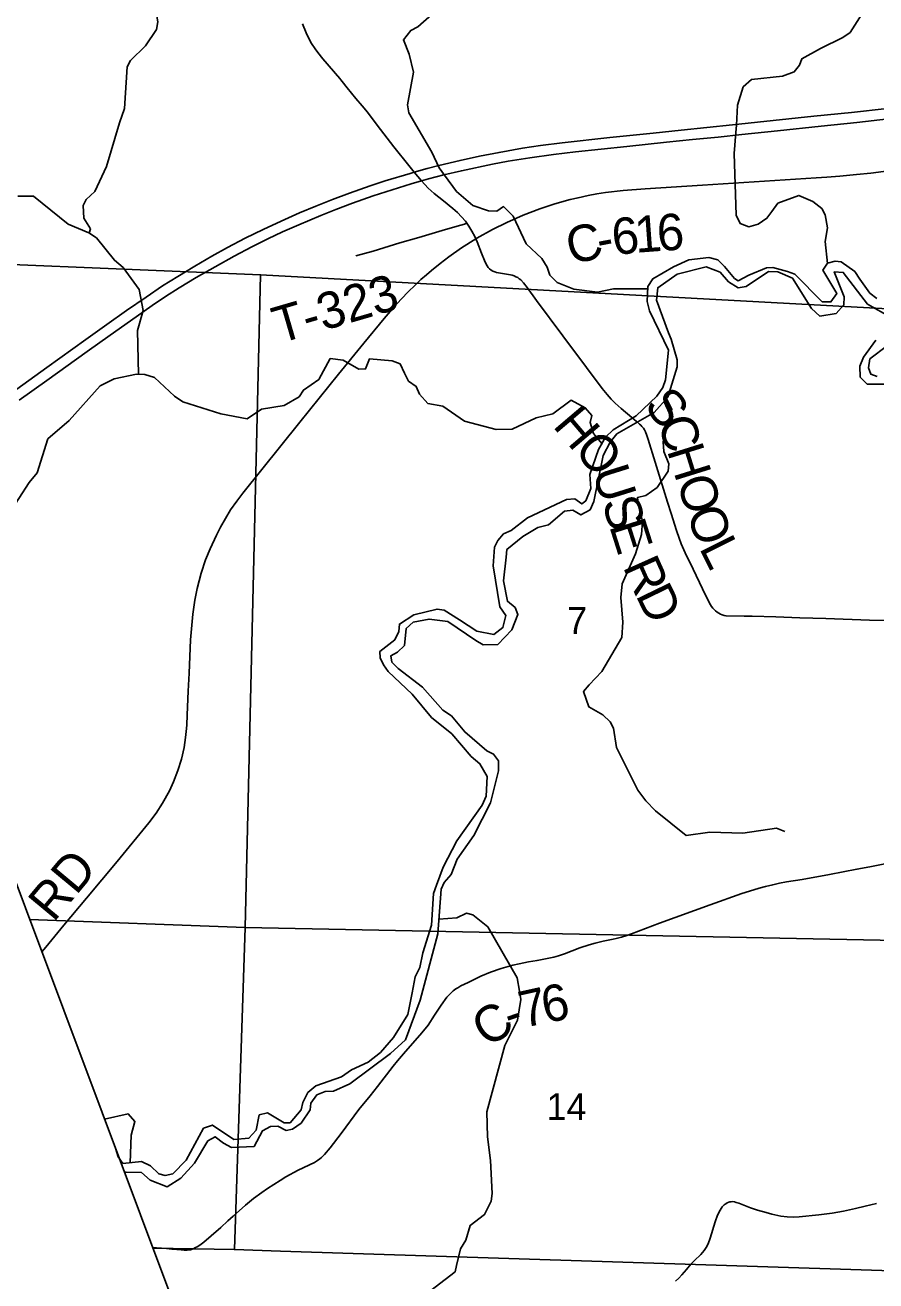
# Model space of a CAD drawing. Extents: x 0 to 34, y 0 to 22.
# Drawn here: x 26.74 to 28.066, y 15.361 to 17.319 of the extents above; entities that cross this region are included whole.
import ezdxf

# ---------------------------------------------------------------- set-up
doc = ezdxf.new("R2010")
doc.units = 0
for name, color, linetype in [('GM_X_County_Road', 7, 'Continuous'), ('GM_X_County_Road_Text', 7, 'Continuous'), ('GM_X_Minor_River', 7, 'Continuous'), ('GM_X_Section', 7, 'Continuous'), ('GM_X_Section_Text', 7, 'Continuous'), ('GM_X_State_Route', 7, 'Continuous'), ('GM_X_Township_Road', 7, 'Continuous'), ('GM_X_Township_Road_Text', 7, 'Continuous'), ('SH_Text', 7, 'Continuous')]:
    doc.layers.add(name, color=color, linetype=linetype)

msp = doc.modelspace()

# ---------------------------------------------------------------- linework, layer by layer
at = {"layer": 'GM_X_County_Road'}
for points in [[(27.4423, 16.9857), (27.4438, 16.9866), (27.4682, 17.0003), (27.4904, 17.0113), (27.5159, 17.0225), (27.542, 17.0326), (27.5655, 17.0403), (27.5895, 17.0468), (27.6017, 17.0497), (27.6176, 17.0531), (27.6308, 17.0555), (27.6442, 17.0578), (27.6719, 17.0611), (27.7063, 17.0637), (27.7954, 17.0692), (27.9725, 17.0806), (27.9895, 17.0818), (28.0098, 17.0832), (28.0357, 17.0857), (28.0579, 17.088), (28.0778, 17.0905), (28.1024, 17.0939), (28.1087, 17.095)], [(26.7658, 15.8742), (26.772, 15.8816), (26.8004, 15.9156), (26.8357, 15.958), (26.8836, 16.0152), (26.933, 16.0753), (26.9441, 16.0903), (26.9541, 16.1061), (26.9648, 16.1251), (26.9714, 16.1393), (26.9781, 16.1568), (26.9835, 16.1747), (26.9877, 16.1929), (26.9901, 16.2083), (26.9911, 16.2178), (26.9919, 16.2275), (26.9927, 16.2437), (26.9943, 16.2805), (26.9957, 16.3086), (26.9979, 16.3605), (27.0014, 16.4007), (27.0043, 16.4222), (27.008, 16.4404), (27.0145, 16.4644), (27.0213, 16.485), (27.0281, 16.5023), (27.0382, 16.5238), (27.0444, 16.5359), (27.052, 16.5498), (27.0602, 16.5629), (27.0701, 16.5766), (27.0792, 16.589), (27.1683, 16.6996), (27.2285, 16.7747), (27.2679, 16.8228), (27.2993, 16.8613), (27.3154, 16.8801), (27.326, 16.8914), (27.3374, 16.9035), (27.3473, 16.9131), (27.3568, 16.9221), (27.3652, 16.9295), (27.3731, 16.9364), (27.3868, 16.9472), (27.4, 16.9574), (27.4202, 16.9718), (27.4423, 16.9857)], [(26.9385, 15.4132), (26.9448, 15.4129), (26.9602, 15.4115), (26.9687, 15.4107), (26.9766, 15.41), (26.9832, 15.4095), (26.9878, 15.4093), (26.9903, 15.4092), (26.9927, 15.4092), (26.9947, 15.4094), (26.9975, 15.4098), (26.9991, 15.4103), (27.0017, 15.4112), (27.0055, 15.4131), (27.0081, 15.4145), (27.0109, 15.416), (27.0144, 15.4184), (27.0184, 15.4216), (27.0298, 15.4315), (27.0447, 15.4445), (27.0559, 15.4549), (27.0643, 15.4623), (27.0833, 15.4792), (27.0958, 15.4896), (27.109, 15.4992), (27.1178, 15.5052), (27.1275, 15.5114), (27.1374, 15.5178), (27.1464, 15.5234), (27.1656, 15.5336), (27.1907, 15.5458), (27.1955, 15.5488), (27.1991, 15.5512), (27.2019, 15.5536), (27.2049, 15.5566), (27.2066, 15.5584), (27.2152, 15.5687), (27.2323, 15.5908), (27.2601, 15.6282), (27.2777, 15.6499), (27.2891, 15.6642), (27.3137, 15.696), (27.3203, 15.704), (27.3297, 15.715), (27.3584, 15.7477), (27.3678, 15.7599), (27.378, 15.7754), (27.3881, 15.7911), (27.3974, 15.8036), (27.4, 15.8067), (27.4039, 15.8104), (27.4069, 15.8131), (27.4112, 15.8163), (27.4143, 15.8182), (27.4192, 15.8211), (27.4302, 15.8265), (27.45, 15.836), (27.465, 15.8423), (27.4819, 15.8483), (27.4999, 15.8532), (27.51, 15.8556), (27.5244, 15.8583), (27.5379, 15.8608), (27.5559, 15.864), (27.5637, 15.8657), (27.5714, 15.8677), (27.5805, 15.8708), (27.6044, 15.8802), (27.6191, 15.885), (27.6282, 15.8876), (27.6408, 15.8906), (27.6564, 15.8939), (27.6612, 15.895), (27.6693, 15.8972), (27.6759, 15.8993), (27.6851, 15.9023), (27.7287, 15.9186), (27.8073, 15.9476), (27.8571, 15.965), (27.8689, 15.9689), (27.8838, 15.9734), (27.8935, 15.9761), (27.9049, 15.9788), (27.9153, 15.9811), (27.9263, 15.983), (27.9508, 15.9871), (27.9935, 15.9949), (28.0362, 16.0028), (28.0564, 16.0068), (28.0875, 16.013)]]:
    msp.add_lwpolyline(points, dxfattribs=at)
at = {"layer": 'GM_X_Minor_River'}
for points in [[(26.8399, 16.9945), (26.8418, 17.0014), (26.8315, 17.0177), (26.8303, 17.0374), (26.8352, 17.0469), (26.8487, 17.0595), (26.8668, 17.0986), (26.8869, 17.1662), (26.8948, 17.1887), (26.899, 17.2539), (26.9043, 17.2638), (26.9276, 17.2863), (26.9449, 17.3118), (26.9468, 17.3239), (26.9425, 17.347), (26.9406, 17.3595), (26.9127, 17.4198), (26.8967, 17.4455), (26.8591, 17.5429)], [(27.7104, 16.9077), (27.6568, 16.9076), (27.6319, 16.9022), (27.5951, 16.907), (27.569, 16.9175), (27.5579, 16.9288), (27.5537, 16.9414), (27.5453, 16.955), (27.521, 16.978), (27.5004, 17.0208), (27.4855, 17.0359), (27.475, 17.0287), (27.4621, 17.029), (27.4375, 17.0377), (27.4124, 17.0592), (27.3934, 17.0846), (27.3854, 17.0963), (27.3739, 17.1209), (27.3377, 17.1819), (27.3357, 17.1944), (27.345, 17.2456), (27.3384, 17.2737), (27.3296, 17.296), (27.3409, 17.3105), (27.3518, 17.3162), (27.3865, 17.3467)], [(27.9901, 16.9473), (27.9869, 16.9813), (27.9902, 17.0025), (27.9868, 17.023), (27.9814, 17.0328), (27.9674, 17.0438), (27.9457, 17.0532), (27.9132, 17.0413), (27.9035, 17.0284), (27.8959, 17.0177), (27.8823, 17.0086), (27.8676, 17.0043), (27.854, 17.0096), (27.8478, 17.0225), (27.8448, 17.1188), (27.8473, 17.1515), (27.8484, 17.1628), (27.8501, 17.194), (27.8587, 17.2224), (27.8719, 17.2339), (27.9203, 17.2394), (27.9385, 17.2459), (27.9468, 17.2561), (27.9505, 17.2664), (27.9796, 17.2821), (28.0143, 17.2993), (28.0256, 17.3073), (28.0437, 17.3358)], [(26.9164, 16.7744), (26.9152, 16.8427), (26.9241, 16.8739), (26.9175, 16.9065), (26.8928, 16.9409), (26.8791, 16.9522), (26.851, 16.9871), (26.8392, 16.995), (26.807, 17.0085), (26.753, 17.052), (26.7288, 17.0519)], [(28.0672, 16.8928), (28.0565, 16.9007), (28.0409, 16.9227), (28.0329, 16.9348), (28.0117, 16.9495), (28.0022, 16.951), (27.9905, 16.9479), (27.9833, 16.9369), (28.0047, 16.9005), (27.9957, 16.8872), (27.982, 16.8875), (27.9395, 16.9306), (27.9281, 16.9348), (27.905, 16.9411), (27.8951, 16.9403), (27.8679, 16.9292), (27.851, 16.9202), (27.8454, 16.924), (27.83, 16.9427), (27.8194, 16.9529), (27.8054, 16.9567), (27.774, 16.9528), (27.7502, 16.9421)], [(27.7502, 16.9421), (27.7181, 16.9234), (27.7105, 16.9112), (27.7095, 16.8877), (27.713, 16.8736), (27.7428, 16.8123), (27.738, 16.7656), (27.7339, 16.7538), (27.7245, 16.7401), (27.692, 16.7096), (27.6566, 16.6879), (27.6446, 16.6765), (27.6337, 16.6571), (27.6198, 16.618), (27.6214, 16.5964), (27.6136, 16.5773), (27.6075, 16.5724), (27.5965, 16.5803), (27.5837, 16.5791), (27.5228, 16.5505), (27.4972, 16.531), (27.4855, 16.5257), (27.4768, 16.5154), (27.4716, 16.5051), (27.4694, 16.4759), (27.4795, 16.4118), (27.4891, 16.3986), (27.4846, 16.3796), (27.4703, 16.3689), (27.4437, 16.3738), (27.4168, 16.3915), (27.3929, 16.4066), (27.3819, 16.4084), (27.3456, 16.3996), (27.3233, 16.3851), (27.3222, 16.3733), (27.3159, 16.3604), (27.2928, 16.3425), (27.2933, 16.3323), (27.2982, 16.3216), (27.3055, 16.311), (27.3431, 16.2759), (27.3732, 16.2396), (27.4051, 16.2139), (27.4351, 16.1787), (27.4488, 16.1674), (27.4599, 16.1477), (27.4585, 16.1166), (27.4521, 16.1025), (27.4126, 16.047), (27.3912, 16.0059), (27.3811, 15.9778), (27.3766, 15.9649), (27.3734, 15.9156), (27.36, 15.8727), (27.3552, 15.8499), (27.3478, 15.835), (27.3432, 15.81), (27.3362, 15.7766), (27.314, 15.7405), (27.294, 15.7173), (27.2744, 15.702), (27.2487, 15.6902), (27.2329, 15.6791), (27.1928, 15.6653), (27.1804, 15.6546), (27.1729, 15.6394), (27.1703, 15.6277), (27.1529, 15.6075), (27.1437, 15.6075), (27.1177, 15.6229), (27.1048, 15.6198), (27.1, 15.5963), (27.0887, 15.5834), (27.0652, 15.5818), (27.0318, 15.604), (27.0182, 15.5991), (26.9908, 15.5493), (26.9701, 15.5283), (26.958, 15.5256), (26.9485, 15.5279), (26.9356, 15.5407), (26.9212, 15.5471), (26.8924, 15.544), (26.8852, 15.5546), (26.8806, 15.5679), (26.876, 15.5807), (26.8758, 15.5807)], [(26.8944, 15.5311), (26.8974, 15.5304), (26.9212, 15.5301), (26.9349, 15.518), (26.9611, 15.5078), (26.9826, 15.5215), (27.0037, 15.5448), (27.0247, 15.5794), (27.0361, 15.5858), (27.049, 15.576), (27.0615, 15.5689), (27.0968, 15.5708), (27.1098, 15.5952), (27.1223, 15.6021), (27.1337, 15.6025), (27.1469, 15.5957), (27.1568, 15.5976), (27.17, 15.6072), (27.1843, 15.6277), (27.185, 15.638), (27.1948, 15.6513), (27.2076, 15.6566), (27.2205, 15.6571), (27.2458, 15.6681), (27.3096, 15.7158), (27.3329, 15.7371), (27.3554, 15.799), (27.3829, 15.9023), (27.3883, 15.9718), (27.3928, 15.9824), (27.4037, 15.9946), (27.4131, 16.0185), (27.4391, 16.0554), (27.4653, 16.1064), (27.4776, 16.1561), (27.4775, 16.1721), (27.4699, 16.1823), (27.4597, 16.1875), (27.4251, 16.217), (27.4042, 16.242), (27.3909, 16.2507), (27.359, 16.2866), (27.3214, 16.316), (27.3115, 16.3259), (27.3099, 16.3357), (27.3205, 16.3411), (27.3314, 16.3517), (27.3336, 16.3779), (27.3449, 16.3878), (27.3695, 16.3928), (27.3986, 16.3892), (27.4423, 16.3597), (27.4537, 16.3529), (27.4764, 16.3534), (27.4982, 16.3759), (27.508, 16.3998), (27.5034, 16.4108), (27.4916, 16.4206), (27.4854, 16.4525), (27.4894, 16.4896), (27.4909, 16.5014), (27.5154, 16.5216), (27.5392, 16.5357), (27.5558, 16.5396), (27.5803, 16.5609), (27.5936, 16.5625), (27.6061, 16.5553), (27.6204, 16.5633), (27.6261, 16.5759), (27.6409, 16.6478), (27.6515, 16.6686), (27.6621, 16.6815), (27.7201, 16.7151), (27.7416, 16.7387), (27.7561, 16.7858), (27.7561, 16.7972), (27.7469, 16.829), (27.7426, 16.8392), (27.7239, 16.89), (27.7257, 16.9094), (27.7559, 16.9307), (27.8013, 16.9419), (27.8229, 16.9336), (27.8362, 16.9185), (27.851, 16.9091)], [(26.8944, 15.5311), (26.8974, 15.5304), (26.9212, 15.5301), (26.9349, 15.518), (26.9611, 15.5078), (26.9826, 15.5215), (27.0037, 15.5448), (27.0247, 15.5794), (27.0361, 15.5858), (27.049, 15.576), (27.0615, 15.5689), (27.0968, 15.5708), (27.1098, 15.5952), (27.1223, 15.6021), (27.1337, 15.6025), (27.1469, 15.5957), (27.1568, 15.5976), (27.17, 15.6072), (27.1843, 15.6277), (27.185, 15.638), (27.1948, 15.6513), (27.2076, 15.6566), (27.2205, 15.6571), (27.2458, 15.6681), (27.3096, 15.7158), (27.3329, 15.7371), (27.3554, 15.799), (27.3829, 15.9023), (27.3883, 15.9718), (27.3928, 15.9824), (27.4037, 15.9946), (27.4131, 16.0185), (27.4391, 16.0554), (27.4653, 16.1064), (27.4776, 16.1561), (27.4775, 16.1721), (27.4699, 16.1823), (27.4597, 16.1875), (27.4251, 16.217), (27.4042, 16.242), (27.3909, 16.2507), (27.359, 16.2866), (27.3214, 16.316), (27.3115, 16.3259), (27.3099, 16.3357), (27.3205, 16.3411), (27.3314, 16.3517), (27.3336, 16.3779), (27.3449, 16.3878), (27.3695, 16.3928), (27.3986, 16.3892), (27.4423, 16.3597), (27.4537, 16.3529), (27.4764, 16.3534), (27.4982, 16.3759), (27.508, 16.3998), (27.5034, 16.4108), (27.4916, 16.4206), (27.4854, 16.4525), (27.4894, 16.4896), (27.4909, 16.5014), (27.5154, 16.5216), (27.5392, 16.5357), (27.5558, 16.5396), (27.5803, 16.5609), (27.5936, 16.5625), (27.6061, 16.5553), (27.6204, 16.5633), (27.6261, 16.5759), (27.6409, 16.6478), (27.6515, 16.6686), (27.6621, 16.6815), (27.7201, 16.7151), (27.7416, 16.7387), (27.7561, 16.7858), (27.7561, 16.7972), (27.7469, 16.829), (27.7426, 16.8392), (27.7239, 16.89), (27.7257, 16.9094), (27.7559, 16.9307), (27.8013, 16.9419), (27.8229, 16.9336), (27.8362, 16.9185), (27.851, 16.9091)], [(27.851, 16.9091), (27.8635, 16.9114), (27.8986, 16.9346), (27.9129, 16.9339), (27.9357, 16.9245), (27.9654, 16.8772), (27.9783, 16.8651), (28.0037, 16.8694), (28.0157, 16.8827), (28.0161, 16.8953), (28.0008, 16.9343), (28.0148, 16.9332), (28.0525, 16.884), (28.0896, 16.8629)], [(28.0659, 16.8275), (28.0464, 16.8013), (28.0408, 16.7872), (28.0412, 16.7701), (28.0522, 16.7588), (28.098, 16.759)], [(28.0677, 16.771), (28.0578, 16.7744), (28.0544, 16.7846), (28.0562, 16.7983), (28.0841, 16.8192)], [(27.6388, 16.6663), (27.6256, 16.6821), (27.6206, 16.6995), (27.6232, 16.7102), (27.6129, 16.7223), (27.5909, 16.734), (27.5623, 16.713), (27.5366, 16.7064), (27.4992, 16.6889), (27.4738, 16.6884), (27.4249, 16.7015), (27.3911, 16.7249), (27.3673, 16.729), (27.3547, 16.7434), (27.3494, 16.7555), (27.3372, 16.7638), (27.3311, 16.7763), (27.3242, 16.7907), (27.3121, 16.7956), (27.2765, 16.7985), (27.2705, 16.7829), (27.2599, 16.7825), (27.2356, 16.7964), (27.2155, 16.799), (27.1975, 16.7663), (27.1737, 16.7499), (27.167, 16.7393), (27.1439, 16.7259), (27.1084, 16.7201), (27.0861, 16.7052), (27.0452, 16.713), (26.9857, 16.7314), (26.9728, 16.7405), (26.9416, 16.7692), (26.9265, 16.7741), (26.9136, 16.7744), (26.8788, 16.7675), (26.8569, 16.7564), (26.8087, 16.7024), (26.7755, 16.6738), (26.7587, 16.6206), (26.7462, 16.6058), (26.6977, 16.5309)], [(27.7397, 16.7366), (27.748, 16.72), (27.7342, 16.6691), (27.7354, 16.6543), (27.7431, 16.6346), (27.742, 16.6236), (27.7247, 16.5978), (27.7073, 16.5855), (27.6944, 16.5824), (27.6952, 16.5726), (27.7018, 16.5453), (27.7004, 16.5248), (27.6914, 16.4948), (27.6704, 16.4477), (27.6682, 16.4264), (27.6715, 16.3881), (27.6697, 16.3642), (27.6388, 16.3109), (27.6192, 16.2904), (27.6102, 16.2797), (27.6186, 16.2558), (27.6403, 16.2438), (27.6517, 16.2329), (27.6567, 16.223), (27.6614, 16.1927), (27.695, 16.1261), (27.7072, 16.1094), (27.7221, 16.094), (27.77, 16.0555), (27.8071, 16.0606), (27.8583, 16.0589), (27.9109, 16.0668), (27.9238, 16.0619)], [(27.3847, 15.9249), (27.4128, 15.9271), (27.4276, 15.9344), (27.4378, 15.9318), (27.461, 15.9133), (27.5065, 15.8338), (27.5104, 15.8126), (27.5123, 15.7997), (27.5072, 15.7678), (27.4877, 15.7283), (27.4593, 15.6246), (27.4603, 15.5859), (27.465, 15.5491), (27.4679, 15.4972), (27.466, 15.4854), (27.4559, 15.4645), (27.4336, 15.4477), (27.4265, 15.4245), (27.4182, 15.4112), (27.4123, 15.385), (27.4101, 15.3755)], [(26.8635, 15.6135), (26.9003, 15.6217), (26.911, 15.6096), (26.9054, 15.5884), (26.9035, 15.5452)], [(27.4101, 15.3755), (27.3568, 15.3343), (27.3167, 15.3186), (27.2997, 15.3151), (27.2845, 15.3203), (27.2614, 15.3194), (27.2527, 15.3061)]]:
    msp.add_lwpolyline(points, dxfattribs=at)
at = {"layer": 'GM_X_Section'}
for points in [[(26.4812, 16.9552), (27.1069, 16.9297), (27.0827, 15.9122), (26.747, 15.9245)], [(26.747, 15.9245), (27.0827, 15.9122), (27.0662, 15.41), (26.9388, 15.4124)]]:
    msp.add_lwpolyline(points, dxfattribs=at)
for points in [[(27.1069, 16.9297), (28.1132, 16.8751), (28.0983, 15.8917), (27.0827, 15.9122)], [(27.0827, 15.9122), (28.0983, 15.8917), (28.0913, 15.3767), (27.6233, 15.3921), (27.138, 15.4077), (27.0662, 15.41)]]:
    msp.add_lwpolyline(points, close=True, dxfattribs=at)
at = {"layer": 'GM_X_State_Route'}
for points in [[(26.6554, 16.7), (26.7739, 16.7852), (26.8346, 16.8285), (26.8673, 16.8521), (26.8977, 16.8737), (26.9284, 16.8949), (26.9542, 16.9121), (26.9777, 16.9271), (27.0042, 16.9432), (27.0311, 16.9587), (27.0556, 16.9721), (27.0831, 16.9864), (27.111, 17.0001), (27.139, 17.0133), (27.1674, 17.0259), (27.1932, 17.0367), (27.2191, 17.0471), (27.2453, 17.0568), (27.2775, 17.0681), (27.3011, 17.0758), (27.3398, 17.0875), (27.3464, 17.0894), (27.3666, 17.0952), (27.3846, 17.0999), (27.4178, 17.1079), (27.4482, 17.1145), (27.4786, 17.1204), (27.5153, 17.1268), (27.543, 17.1309), (27.5768, 17.1352), (27.6509, 17.1435), (27.7189, 17.1505), (27.7621, 17.155), (27.8023, 17.1591), (27.8424, 17.1633), (27.969, 17.1766), (28.0277, 17.1827), (28.0833, 17.1886)], [(26.7309, 16.734), (26.7739, 16.7645), (26.8369, 16.8099), (26.8723, 16.8352), (26.9128, 16.8641), (26.9382, 16.8819), (26.9589, 16.8958), (26.9798, 16.9091), (27.0064, 16.9252), (27.036, 16.9422), (27.0659, 16.9587), (27.0934, 16.9732), (27.1184, 16.9857), (27.1409, 16.9963), (27.1665, 17.0075), (27.2009, 17.0219), (27.224, 17.0312), (27.2502, 17.041), (27.2824, 17.0524), (27.3119, 17.0622), (27.3416, 17.0714), (27.3577, 17.076), (27.3685, 17.0792), (27.3925, 17.0854), (27.4198, 17.0917), (27.4684, 17.1019), (27.4929, 17.1065), (27.5266, 17.112), (27.5635, 17.1172), (27.5975, 17.1213), (27.6778, 17.1296), (27.7396, 17.1361), (27.7798, 17.1402), (27.8199, 17.1443), (27.857, 17.1481), (27.9126, 17.154), (27.9805, 17.1614), (28.0361, 17.1672), (28.0855, 17.1725)]]:
    msp.add_lwpolyline(points, dxfattribs=at)
at = {"layer": 'GM_X_Township_Road'}
for points in [[(27.4283, 17.0098), (27.426, 17.013), (27.42, 17.0201), (27.4136, 17.0269), (27.4066, 17.033), (27.3921, 17.0447), (27.3776, 17.0564), (27.3683, 17.0644), (27.3577, 17.076), (27.3464, 17.0894), (27.3379, 17.0997), (27.3148, 17.1289), (27.2939, 17.1559), (27.2809, 17.1733), (27.2733, 17.1832), (27.2654, 17.1927), (27.2554, 17.2045), (27.2416, 17.2212), (27.234, 17.2308), (27.2321, 17.2332), (27.2303, 17.2356), (27.2041, 17.2661), (27.1961, 17.2763), (27.192, 17.282), (27.1864, 17.2903), (27.182, 17.2978), (27.1777, 17.3067), (27.172, 17.3209)], [(27.2555, 16.9593), (27.2823, 16.9666), (27.3237, 16.9792), (27.3534, 16.9879), (27.395, 17), (27.4187, 17.0069), (27.4246, 17.0087), (27.4283, 17.0098)], [(27.4423, 16.9857), (27.4407, 16.9893), (27.4363, 16.9975), (27.4314, 17.0054), (27.4283, 17.0098)], [(28.0952, 16.3904), (28.0557, 16.3914), (27.9875, 16.3935), (27.9471, 16.3949), (27.9099, 16.3961), (27.8727, 16.3972), (27.8603, 16.3973), (27.8324, 16.3978), (27.8294, 16.3985), (27.8264, 16.3994), (27.8235, 16.4005), (27.8208, 16.4019), (27.8182, 16.4035), (27.8158, 16.4055), (27.8136, 16.4077), (27.8116, 16.41), (27.8098, 16.4125), (27.8081, 16.4152), (27.8051, 16.4206), (27.7957, 16.4402), (27.7808, 16.4709), (27.7686, 16.4961), (27.7624, 16.5103), (27.759, 16.519), (27.7549, 16.5307), (27.7467, 16.5573), (27.7411, 16.5751), (27.722, 16.6374), (27.7111, 16.673), (27.709, 16.6789), (27.7068, 16.6845), (27.7051, 16.6881), (27.7036, 16.6905), (27.7012, 16.6933), (27.6993, 16.6952), (27.6972, 16.6969), (27.6926, 16.701), (27.6854, 16.707), (27.6688, 16.7209), (27.6596, 16.7293), (27.653, 16.7359), (27.6469, 16.7428), (27.6391, 16.7525), (27.6149, 16.7849), (27.5778, 16.8346), (27.5371, 16.8895), (27.5225, 16.9096), (27.5168, 16.917), (27.5125, 16.9215), (27.5101, 16.9234), (27.5076, 16.9251), (27.5049, 16.9266), (27.502, 16.9278), (27.4991, 16.9288), (27.4961, 16.9296), (27.49, 16.9307), (27.4808, 16.9319), (27.4747, 16.9331), (27.4717, 16.934), (27.4689, 16.9352), (27.4662, 16.9367), (27.4638, 16.9386), (27.4617, 16.9409), (27.46, 16.9435), (27.4585, 16.9462), (27.4558, 16.9519), (27.4513, 16.9634), (27.4445, 16.9808), (27.4423, 16.9857)], [(27.7537, 15.3606), (27.7589, 15.3655), (27.7632, 15.3705), (27.7706, 15.3789), (27.7774, 15.387), (27.7833, 15.3928), (27.7929, 15.4024), (27.7981, 15.4086), (27.8015, 15.4134), (27.8042, 15.419), (27.8077, 15.4277), (27.8154, 15.4533), (27.8191, 15.4636), (27.8229, 15.4715), (27.8263, 15.4765), (27.8292, 15.4796), (27.8307, 15.4806), (27.832, 15.4814), (27.8338, 15.4826), (27.8368, 15.4839), (27.8384, 15.4842), (27.8402, 15.4845), (27.8425, 15.4847), (27.8452, 15.4844), (27.8482, 15.4836), (27.852, 15.4823), (27.8704, 15.4749), (27.8812, 15.4715), (27.8947, 15.4676), (27.9038, 15.4652), (27.9177, 15.4622), (27.9273, 15.4609), (27.9366, 15.4605), (27.946, 15.4609), (27.977, 15.4639), (27.9978, 15.4669), (28.0153, 15.47), (28.0341, 15.4741), (28.0491, 15.4779), (28.0579, 15.4799), (28.0668, 15.4819)]]:
    msp.add_lwpolyline(points, dxfattribs=at)
at = {"layer": 'SH_Text'}
msp.add_lwpolyline([(26.5011, 16.5809), (27.1585, 14.8261), (26.7275, 14.8261)], close=True, dxfattribs=at)

# ---------------------------------------------------------------- texts
at = {"layer": 'GM_X_County_Road_Text'}
for s, height, rotation, p in [('6', 0.0568, 6.2465, (27.6572, 16.96)), ('1', 0.0568, 4.1564, (27.6915, 16.9638)), ('6', 0.0568, 4.0103, (27.7264, 16.9663)), ('C', 0.0568, 13.6926, (27.5909, 16.945)), ('-', 0.0568, 10.7649, (27.6355, 16.9559)), ('RD', 0.05682, 50.2578, (26.7843, 15.9189)), ('7', 0.0568, 12.4735, (27.5165, 15.7553)), ('6', 0.0568, 11.0119, (27.5503, 15.7627)), ('C', 0.0568, 34.3298, (27.4611, 15.7235)), ('-', 0.0568, 19.2422, (27.4961, 15.7481))]:
    msp.add_text(s, height=height, rotation=rotation, dxfattribs=at).set_placement(p)
at = {"layer": 'GM_X_Section_Text'}
for s, height, p in [('7', 0.0419, (27.5846, 16.3696)), ('14', 0.04186, (27.5526, 15.6119))]:
    msp.add_text(s, height=height, rotation=0, dxfattribs=at).set_placement(p)
at = {"layer": 'GM_X_Township_Road_Text'}
for s, height, rotation, p in [('T-323', 0.05682, 16.2706, (27.1356, 16.822)), ('S', 0.0568, 309.2587, (27.7028, 16.7246)), ('H', 0.0568, 310.4231, (27.5609, 16.6937)), ('C', 0.0568, 289.4323, (27.7245, 16.6995)), ('O', 0.0568, 310.8319, (27.5936, 16.6553)), ('H', 0.0568, 287.3451, (27.7398, 16.656)), ('U', 0.0568, 287.4131, (27.6233, 16.6228)), ('O', 0.0568, 287.3503, (27.7548, 16.6082)), ('S', 0.0568, 287.4123, (27.6383, 16.5751)), ('O', 0.0568, 289.0194, (27.7702, 16.5588)), ('E', 0.0568, 287.6493, (27.6498, 16.5383)), ('L', 0.0568, 296.515, (27.7897, 16.504)), ('R', 0.0568, 294.1319, (27.6708, 16.4747)), ('D', 0.0568, 295.8621, (27.6907, 16.4304))]:
    msp.add_text(s, height=height, rotation=rotation, dxfattribs=at).set_placement(p)

doc.saveas('drawing.dxf')
